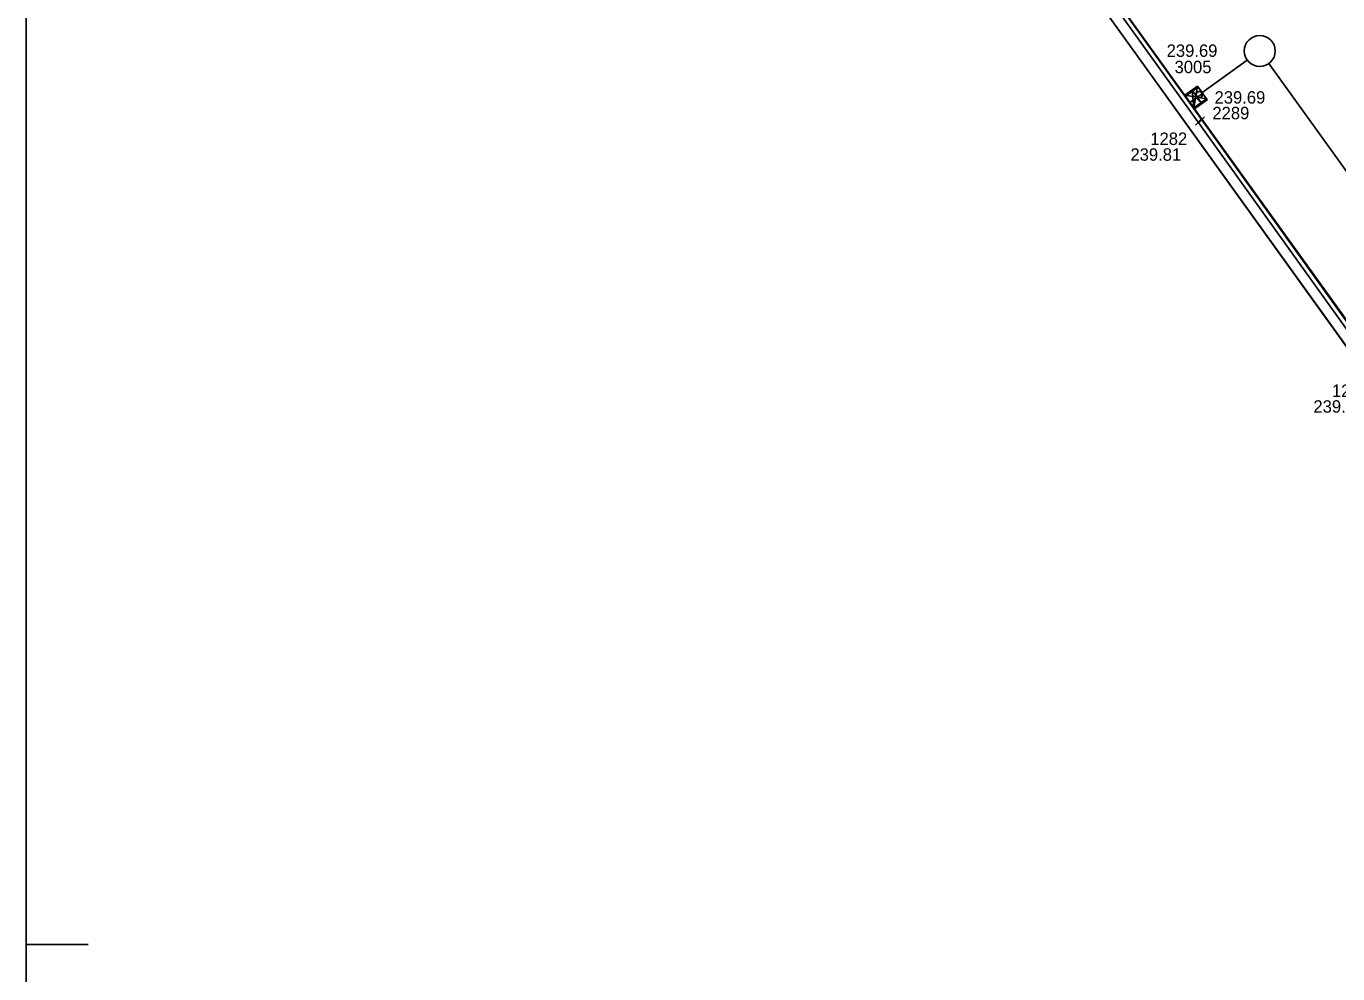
# Model space of a CAD drawing. Extents: x -264222 to -263676, y -1242344 to -1242060.
# Drawn here: x -264222.03 to -264179.73, y -1242246.81 to -1242216.25 of the extents above; entities that cross this region are included whole.
import ezdxf

# ---------------------------------------------------------------- set-up
doc = ezdxf.new("R2010")
doc.units = 0
for name, color, linetype in [('BODY_CISLO', 7, 'Continuous'), ('BODY_SYMBOL', 7, 'Continuous'), ('BODY_VYSKA', 7, 'Continuous'), ('BODY_VYSKY_UV', 7, 'Continuous'), ('KOORDINACNA_SITUACIA_DSP', 7, 'Continuous'), ('PROJEKT_DRS_OBRUBNIKY_KOMUNIKACIE', 7, 'Continuous'), ('PROJEKT_DRS_UV_STAVBY', 7, 'Continuous'), ('RAM_NA_TLAC_8xA4_1-200', 7, 'Continuous'), ('SO_20-3_OBRUBNIKY_DOLNA_HRANA', 7, 'Continuous'), ('SO_20-3_OBRUBNIKY_HORNA_HRANA', 7, 'Continuous'), ('ULICNA_VPUST_POKLOP', 7, 'Continuous')]:
    doc.layers.add(name, color=color, linetype=linetype)

msp = doc.modelspace()

# ---------------------------------------------------------------- linework, layer by layer
at = {"layer": 'BODY_SYMBOL'}
for p, q in [((-264184.378, -1242218.659), (-264184.202, -1242218.483)), ((-264184.202, -1242218.659), (-264184.378, -1242218.483)), ((-264184.314, -1242219.44), (-264184.138, -1242219.264)), ((-264184.138, -1242219.44), (-264184.314, -1242219.264)), ((-264184.198, -1242219.356), (-264184.022, -1242219.18)), ((-264184.022, -1242219.356), (-264184.198, -1242219.18))]:
    msp.add_line(p, q, dxfattribs=at)
at = {"layer": 'KOORDINACNA_SITUACIA_DSP'}
for p, q in [((-264204.694, -1242191.482), (-264122.859, -1242305.266)), ((-264204.078, -1242191.482), (-264122.243, -1242305.266)), ((-264184.115, -1242218.399), (-264182.649, -1242217.344)), ((-264181.951, -1242217.458), (-264153.34, -1242257.238)), ((-264184.659, -1242218.482), (-264184.424, -1242218.313)), ((-264184.367, -1242218.888), (-264184.659, -1242218.482)), ((-264184.424, -1242218.313), (-264184.132, -1242218.719)), ((-264184.424, -1242218.313), (-264184.367, -1242218.888)), ((-264184.424, -1242218.313), (-264184.367, -1242218.888)), ((-264184.132, -1242218.719), (-264184.424, -1242218.313)), ((-264184.132, -1242218.719), (-264184.367, -1242218.888)), ((-264184.367, -1242218.888), (-264184.132, -1242218.719))]:
    msp.add_line(p, q, dxfattribs=at)
msp.add_lwpolyline([(-264204.694, -1242191.482), (-264137.78, -1242284.52), (-264125.581, -1242301.482)], dxfattribs=at)
for centre, radius in [((-264182.243, -1242217.052), 0.5), ((-264184.194, -1242218.461), 0.1)]:
    msp.add_circle(centre, radius, dxfattribs=at)
at = {"layer": 'PROJEKT_DRS_OBRUBNIKY_KOMUNIKACIE'}
for p, q in [((-264204.694, -1242191.482), (-264115.871, -1242314.982)), ((-264204.078, -1242191.482), (-264119.571, -1242308.982))]:
    msp.add_line(p, q, dxfattribs=at)
msp.add_lwpolyline([(-264204.694, -1242191.482), (-264137.78, -1242284.52), (-264125.581, -1242301.482)], dxfattribs=at)
at = {"layer": 'PROJEKT_DRS_UV_STAVBY'}
msp.add_lwpolyline([(-264184.367, -1242218.888), (-264184.659, -1242218.482), (-264184.253, -1242218.19), (-264183.961, -1242218.596), (-264184.367, -1242218.888), (-264184.253, -1242218.19), (-264184.659, -1242218.482), (-264183.961, -1242218.596)], dxfattribs=at)
at = {"layer": 'RAM_NA_TLAC_8xA4_1-200'}
msp.add_line((-264222.03, -1242245.866), (-264220.03, -1242245.866), dxfattribs=at)
msp.add_lwpolyline([(-264222.03, -1242186.466), (-264054.03, -1242186.466), (-264054.03, -1242305.266), (-264222.03, -1242305.266)], close=True, dxfattribs=at)
at = {"layer": 'SO_20-3_OBRUBNIKY_DOLNA_HRANA'}
msp.add_lwpolyline([(-264179.08, -1242196.474), (-264200.47, -1242196.472), (-264195.765, -1242203.023), (-264189.923, -1242211.168), (-264184.11, -1242219.268), (-264178.281, -1242227.391), (-264171.252, -1242237.149), (-264164.83, -1242246.079), (-264158.406, -1242254.997), (-264151.981, -1242263.929), (-264145.549, -1242272.885), (-264139.496, -1242281.305), (-264132.148, -1242291.541), (-264125.165, -1242301.265), (-264124.808, -1242301.762)], dxfattribs=at)
at = {"layer": 'SO_20-3_OBRUBNIKY_HORNA_HRANA'}
msp.add_lwpolyline([(-264204.226, -1242191.388), (-264204.22, -1242191.499), (-264200.55, -1242196.62), (-264195.884, -1242203.112), (-264190.046, -1242211.249), (-264184.226, -1242219.352), (-264178.398, -1242227.475), (-264171.378, -1242237.231), (-264164.951, -1242246.159), (-264158.525, -1242255.075), (-264152.106, -1242264.005), (-264145.671, -1242272.964), (-264139.631, -1242281.361), (-264132.272, -1242291.613), (-264125.285, -1242301.347), (-264124.926, -1242301.846)], dxfattribs=at)
at = {"layer": 'ULICNA_VPUST_POKLOP'}
msp.add_line((-264184.29, -1242218.571), (-264184.29, -1242218.571), dxfattribs=at)
msp.add_lwpolyline([(-264184.495, -1242218.714), (-264184.638, -1242218.51), (-264184.229, -1242218.223), (-264183.942, -1242218.632), (-264184.351, -1242218.919), (-264184.495, -1242218.714), (-264184.085, -1242218.428)], dxfattribs=at)

# ---------------------------------------------------------------- texts
at = {"layer": 'BODY_CISLO'}
for s, p in [('3005', (-264184.99, -1242217.767)), ('2289', (-264183.769, -1242219.253)), ('1282', (-264185.773, -1242220.082)), ('1283', (-264179.914, -1242228.208))]:
    msp.add_text(s, height=0.4, dxfattribs=at).set_placement(p)
at = {"layer": 'BODY_VYSKA'}
for s, p in [('239.69', (-264183.7, -1242218.749)), ('239.81', (-264186.413, -1242220.591)), ('239.69', (-264180.511, -1242228.717))]:
    msp.add_text(s, height=0.4, dxfattribs=at).set_placement(p)
at = {"layer": 'BODY_VYSKY_UV'}
msp.add_text('239.69', height=0.4, dxfattribs=at).set_placement((-264185.245, -1242217.241))

doc.saveas('drawing.dxf')
